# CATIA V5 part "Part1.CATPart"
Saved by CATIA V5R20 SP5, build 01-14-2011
Part number: 垫片
Bounding box of the stored display mesh (mm): x -35 to 35, y -25 to 25, z 0 to 20
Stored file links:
  E:\画图\Part1.CATPart
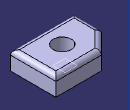
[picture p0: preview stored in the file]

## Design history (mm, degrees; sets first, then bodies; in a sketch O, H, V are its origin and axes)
Body1 (main body)
  Sketch1 on xy-plane, origin (0, 0, 0), H (1, 0, 0), V (0, 1, 0)
    line L1 (35, 25) -> (35, -25)
    line L2 (35, -25) -> (-35, -25)
    line L3 (-35, -25) -> (-35, 5)
    line L4 (-15, 25) -> (35, 25)
    line L5 (-15, 25) -> (-35, 5)
    length L1 = 50
    length L2 = 70
    length L4 = 50
    length L3 = 30
    vertical: L1 V, L3 V
    horizontal: L2 H, L4 H
    equidistance: L1 L3 O, L2 L4 O
  Pad1: profile Sketch1, direction (0, 0, 1), length 20
  Sketch2 on end face of Pad1, origin (1.6017, -1.3484, 20), H (1, 0, 0), V (0, 1, 0)
    point P1 (-0.1862, -0.2184)
  Hole1: placed by Sketch2, at (1.4155, -1.5668, 20) direction (0, 0, -1), diameter 20, through (limit type 3)
  Fillet1: radius 5, on edge [face of Pad1 from Sketch1.L2 | end face of Pad1]; edge [face of Pad1 from Sketch1.L1 | end face of Pad1]; edge [face of Pad1 from Sketch1.L4 | end face of Pad1]; edge [face of Pad1 from Sketch1.L5 | end face of Pad1]; edge [face of Pad1 from Sketch1.L3 | end face of Pad1]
